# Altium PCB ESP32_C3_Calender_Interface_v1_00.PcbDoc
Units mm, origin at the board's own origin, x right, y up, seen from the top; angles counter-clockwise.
Board outline 63.5 x 22.2 mm, 2 copper layers (Top Layer, Bottom Layer), stack 1.671 mm thick; 38 components, 28 nets, 146 pads, 112 vias.
Unrouted connection lines stored in the file: 57.
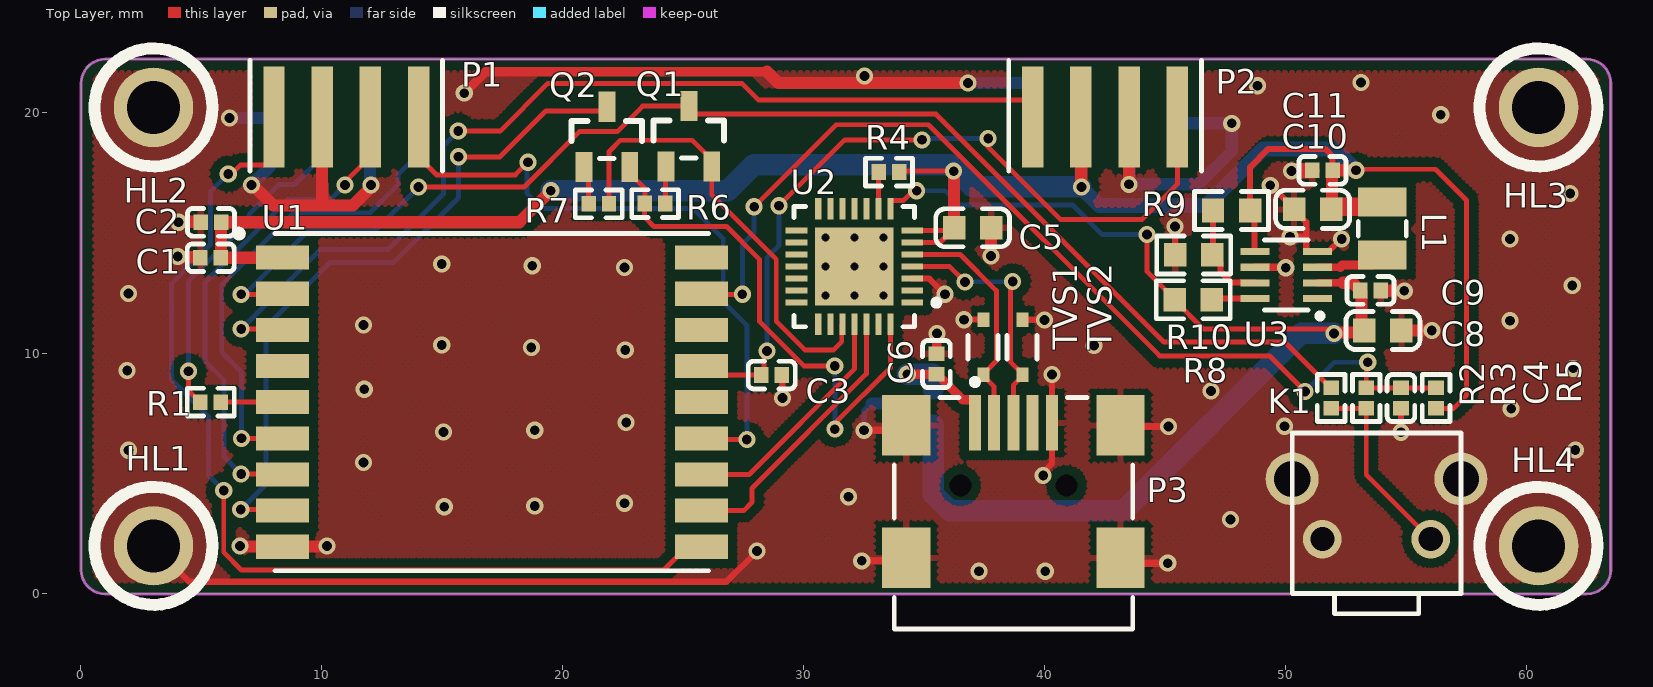
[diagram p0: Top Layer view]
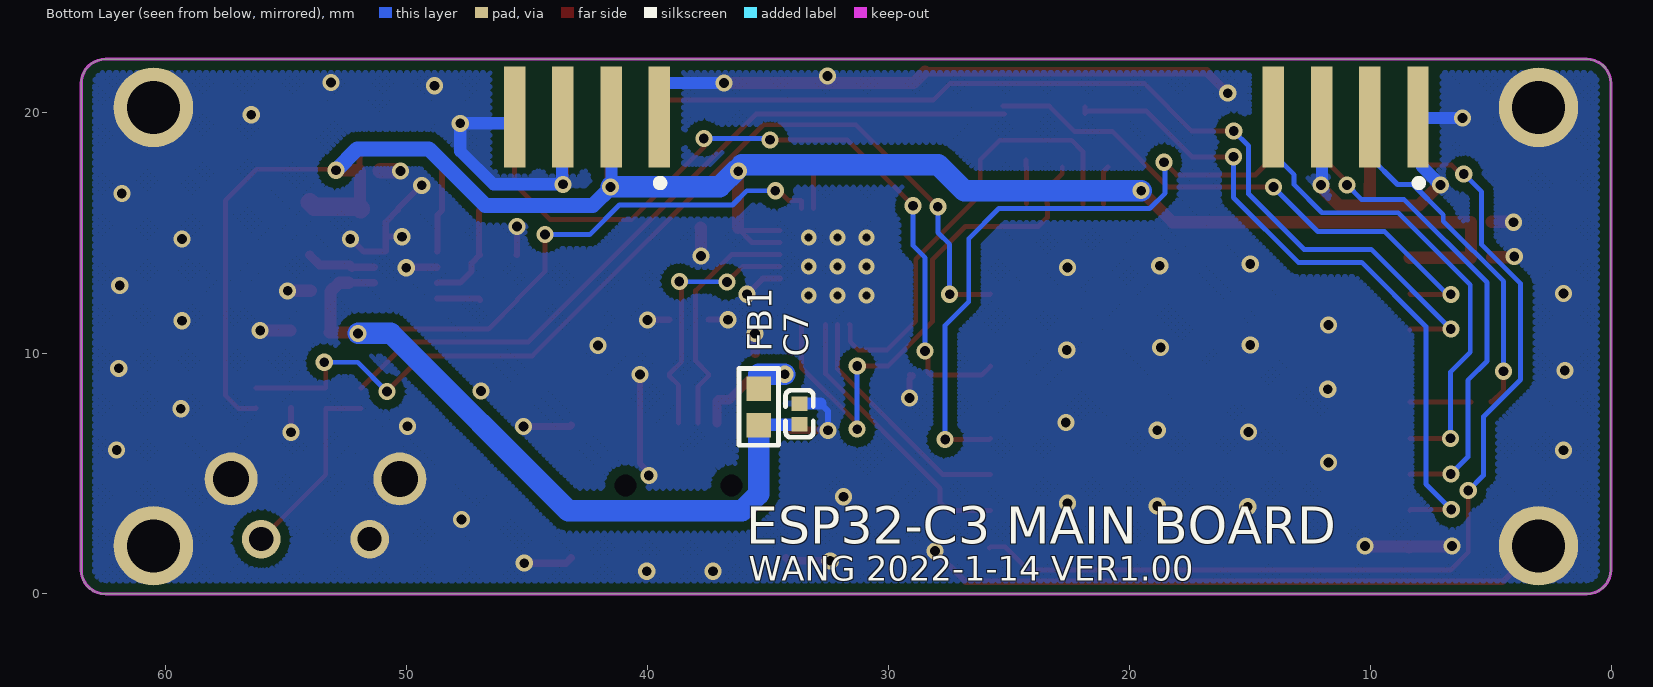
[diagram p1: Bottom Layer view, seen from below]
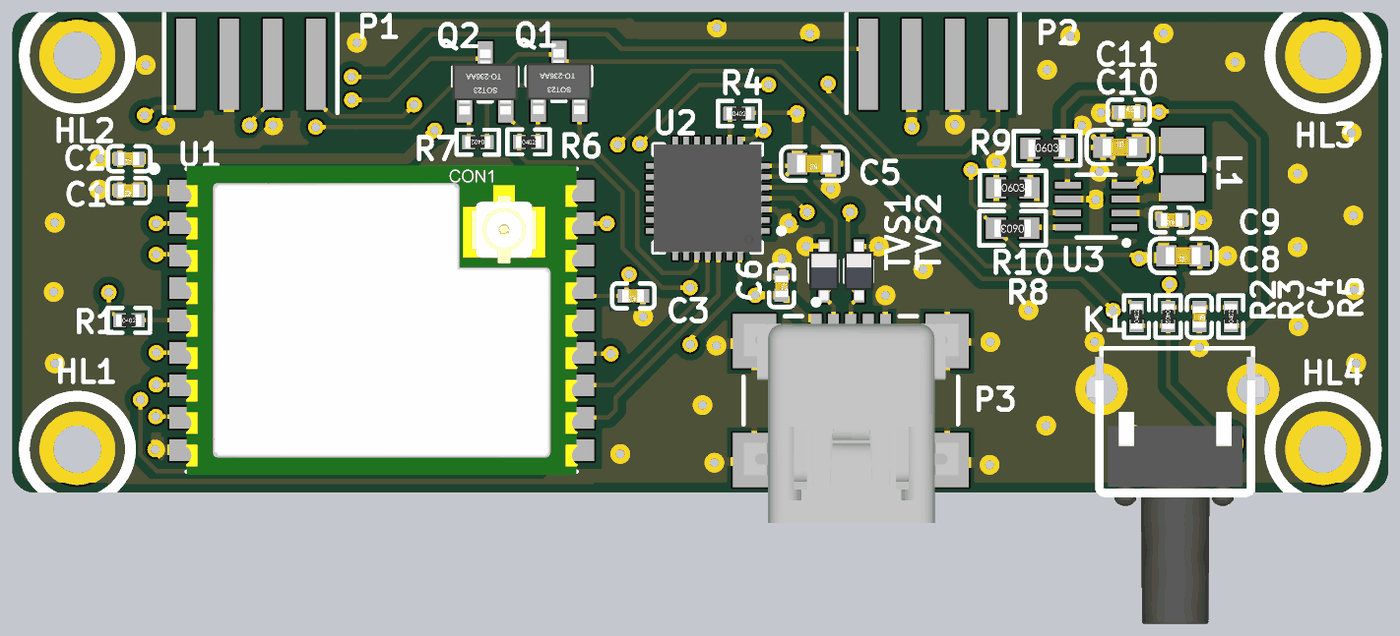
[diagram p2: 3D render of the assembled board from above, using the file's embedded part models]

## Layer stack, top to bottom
Top Solder: solder mask 0.0102, Solder Resist, Dk 3.5
Top Layer: signal copper 0.0356
Dielectric 1: dielectric 1.6, FR-4, Dk 4.8
Bottom Layer: signal copper 0.0356
Bottom Solder: solder mask 0.0102, Solder Resist, Dk 3.5

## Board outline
0.016,1 0.016,21.2 cw(c1.016,21.2) 1.016,22.2 62.516,22.2 cw(c62.516,21.2) 63.516,21.2 63.516,1 cw(c62.516,1) 62.516,0 1.016,0 cw(c1.016,1)

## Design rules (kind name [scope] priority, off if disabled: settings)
Clearance Clearance_1 [InNamedPolygon('GND_TOP') Or  InNamedPolygon('GND_BOTTOM')] p1: gap=0.381 ignorepadtopadclearanceinfootprint=FALSE
Clearance [All] p2: gap=0.152 ignorepadtopadclearanceinfootprint=FALSE
ComponentClearance [All] p1: gap=0.051 collisioncheckmode=3 verticalgap=0 showdistances=FALSE
HoleSize [All] p1: absolutevalues=TRUE maxlimit=5.08 minlimit=0.025 maxpercent=80.000 minpercent=20.000
MinimumSolderMaskSliver [All] p1: minsoldermaskwidth=0
PolygonConnect PolygonConnect_2 [InNet('GND') vs IsThruPin] p1: connectstyle=Direct reliefconductorwidth=0.254 reliefentries=4 polygonreliefangle="90 Angle" airgapwidth=0.254
PolygonConnect PolygonConnect_1 [IsVia] p2: connectstyle=Direct reliefconductorwidth=0.254 reliefentries=4 polygonreliefangle="90 Angle" airgapwidth=0.254
PolygonConnect [All] p3: connectstyle=Relief reliefconductorwidth=0.254 reliefentries=4 polygonreliefangle="90 Angle" airgapwidth=0.254
RoutingVias RoutingVias_1 [InComponent('U1')] p1: holewidth=0.711 width=1.27 viastyle="Through Hole" minholewidth=0.203 minwidth=0.254 maxholewidth=0.711 maxwidth=1.27
RoutingVias [All] p2: holewidth=0.406 width=0.711 viastyle="Through Hole" minholewidth=0.406 minwidth=0.711 maxholewidth=0.711 maxwidth=1.27
SilkToSilkClearance [All] p1: silktosilkclearance=0
SilkToSolderMaskClearance [IsPad] p1: minsilkscreentomaskgap=0 clearancetoexposedcopper=TRUE
SolderMaskExpansion [All] p1: expansion=0.102
Width [All] p1: maxlimit=1.016 minlimit=0.203 preferedwidth=0.254 minimp=50.000000 maximp=50.000000 favimp=50.000000
25 further rules are at their usual default settings.

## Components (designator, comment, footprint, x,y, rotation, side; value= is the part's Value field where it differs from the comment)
C1 "4.7uF (475) 20% 10V" LC-0402_C 5.391,13.958 r180 top
C2 "100nF (104) 10% 16V" LC-0402_C 5.403,15.428 r180 top
C3 "100nF (104) 10% 16V" LC-0402_C 28.679,9.09 r180 top
C4 "100nF (104) 10% 16V" LC-0402_C 54.804,8.132 r270 top
C5 "0.1uF/16V" LC-0603_C 37.023,15.201 r180 top
C6 "100nF (104) 10% 16V" LC-0402_C 35.522,9.549 r270 top
C7 "100nF (104) 10% 16V" LC-0402_C 33.697,7.479 r270 bottom
C8 "10uF (106) 10% 10V" LC-0603_C 54.054,10.938 r180 top
C9 "100nF (104) 10% 16V" LC-0402_C 53.539,12.601 r180 top
C10 "10uF (106) 10% 10V" LC-0603_C 51.136,15.967 r0 top
C11 "100nF (104) 10% 16V" LC-0402_C 51.545,17.585 r0 top
FB1 "Ferrite bread" R0603 35.389,7.764 r90 bottom value=120R@600MHz/500mA
HL1 "D2.0" HOLE_D2.0 3.016,2 r0 top locked
HL2 "D2.0" HOLE_D2.0 3.016,20.2 r0 top locked
HL3 "D2.0" HOLE_D2.0 60.516,20.2 r0 top locked
HL4 "D2.0" HOLE_D2.0 60.516,2 r0 top locked
K1 "BUTTON" BUTTON-TH-6X6-R 53.79,3.475 r0 top locked
L1 "IND" INDM2520X10N 54.027,15.166 r90 top value=1uH/3A
P1 "Header 4X2" HDR2X4-P2-SMD-SIDE-CUSTOM 11.02,17.55 r0 top locked
P2 "Header 4X2" HDR2X4-P2-SMD-SIDE-CUSTOM 42.52,17.55 r0 top locked
P3 "MiniUSB Socket" USB-F-MINI 38.716,7.1 r90 top locked value="mini-USB Socket"
Q1 "SS8050 Y1" LC-SOT-23(SOT-23-3) 25.241,19 r270 top
Q2 "SS8050 Y1" LC-SOT-23(SOT-23-3) 21.836,18.978 r270 top
R1 "22Ω (22R0) ±1%" LC-0402_R 5.391,7.962 r0 top
R2 "0Ω (0R0) ±1%" LC-0402_R 51.904,8.132 r90 top
R3 "0Ω (0R0) ±1%/NC" LC-0402_R 53.365,8.132 r270 top
R4 "4.7KΩ (4701) ±1%" LC-0402_R 33.552,17.517 r0 top
R5 "10KΩ (1002) ±1%" LC-0402_R 56.259,8.132 r90 top
R6 "10KΩ (1002) ±1%" LC-0402_R 23.843,16.207 r0 top
R7 "10KΩ (1002) ±1%" LC-0402_R 21.501,16.196 r180 top
R8 "100KΩ (1003) ±1%" LC-0603_R 46.183,12.212 r180 top
R9 "200KΩ (2003) ±1%" LC-0603_R 47.771,15.918 r0 top
R10 "44.2KΩ (4422) ±1%" LC-0603_R 46.202,14.077 r0 top
TVS1 "PESD3V3L1BA" SOD-323B 37.48,10.242 r90 top
TVS2 "PESD3V3L1BA" SOD-323B 39.092,10.242 r90 top
U1 "ESP32-C3-13U" ESP32-C3-13U 17.062,7.962 r0 top
U2 "CP2102" CP2102 32.113,13.591 r180 top
U3 "MP2161" TSOT23-8 50.043,13.239 r90 top

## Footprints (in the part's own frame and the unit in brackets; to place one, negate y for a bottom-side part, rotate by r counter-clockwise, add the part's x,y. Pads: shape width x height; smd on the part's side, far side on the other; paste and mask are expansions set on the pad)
BUTTON-TH-6X6-R [mm]
  round 1.6 hole 1: 1(-2.25,-1.2) 2(2.25,-1.2)
  round 2.2 hole 1.5: BK1(-3.5,1.3) BK2(3.5,1.3)
  silkscreen extent -3.5,-4.3 3.5,3.2, body extent -4.2,-9.55 4,2.8, height 7.8
CP2102 [mm] "QFN, 28-Leads, Body 5.0x5.0mm (max), Pitch 0.50mm, IPC Medium Density"
  rect 0.9x0.25 smd: 1(-2.4,1.5) 2(-2.4,1) 3(-2.4,0.5) 4(-2.4,0) 5(-2.4,-0.5) 6(-2.4,-1) 7(-2.4,-1.5) 15(2.4,-1.5) 16(2.4,-1) 17(2.4,-0.5) 18(2.4,0) 19(2.4,0.5) 20(2.4,1) 21(2.4,1.5)
  rect 0.25x0.9 smd: 8(-1.5,-2.4) 9(-1,-2.4) 10(-0.5,-2.4) 11(0,-2.4) 12(0.5,-2.4) 13(1,-2.4) 14(1.5,-2.4) 22(1.5,2.4) 23(1,2.4) 24(0.5,2.4) 25(0,2.4) 26(-0.5,2.4) 27(-1,2.4) 28(-1.5,2.4)
  rect 3.25x3.25 smd: 29(0,0)
  silkscreen extent -3.53,-2.5 2.5,2.5, body extent -2.5,-2.5 2.5,2.5, height 1
ESP32-C3-13U [mm] "AI Thinker ESP32-C3-13U Module"
  rect 2.2x1 smd: 1(-8.7,6) 2(-8.7,4.5) 3(-8.7,3) 4(-8.7,1.5) 5(-8.7,0) 6(-8.7,-1.5) 7(-8.7,-3) 8(-8.7,-4.5) 9(-8.7,-6) 10(8.7,-6) 11(8.7,-4.5) 12(8.7,-3) 13(8.7,-1.5) 14(8.7,0) 15(8.7,1.5) 16(8.7,3) 17(8.7,4.5) 18(8.7,6)
  silkscreen extent -10.63,-7 9,7.13, body extent -9.03,-7.15 9.04,7.15, height 3.28
HDR2X4-P2-SMD-SIDE-CUSTOM [mm]
  rect 0.89x4.2 smd far side: 1(-3,2.25) 3(-1,2.25) 5(1,2.25) 7(3,2.25)
  rect 0.89x4.2 smd: 2(-3,2.25) 4(-1,2.25) 6(1,2.25) 8(3,2.25)
  silkscreen extent -4,0 4,4.6
HOLE_D2.0 [mm]
  round 3.3 hole 2.2: 1(0,0)
  silkscreen extent -2.45,-2.45 2.45,2.45
INDM2520X10N [mm] "Molded Inductor, 2-Leads, Body 2.5x2.0mm, IPC Medium Density"
  rect 1.2x2 smd: 1(-1.1,0) 2(1.1,0)
  silkscreen extent -0.3,-1 0.3,1, body extent -1.35,-1.1 1.35,1.1, height 1
LC-0402_C [mm]
  rect 0.6x0.65 smd mask+0.051: 1(-0.425,0) 2(0.425,0)
  silkscreen extent -0.97,-0.58 0.97,0.58, body extent -0.48,-0.3 0.52,0.3, height 0.2
LC-0402_R [mm]
  rect 0.6x0.65 smd mask+0.051: 1(-0.425,0) 2(0.425,0)
  silkscreen extent -0.97,-0.58 0.97,0.58, body extent -0.57,-0.27 0.58,0.28, height 0.41
LC-0603_C [mm]
  rect 0.93x0.98 smd: 1(-0.77,0) 2(0.77,0)
  silkscreen extent -1.53,-0.79 1.54,0.79, body extent -0.8,-0.4 0.8,0.4, height 0.3
LC-0603_R [mm]
  rect 0.93x0.98 smd: 1(-0.77,0) 2(0.77,0)
  silkscreen extent -1.53,-0.79 1.54,0.79, body extent -0.85,-0.4 0.85,0.4, height 0.56
LC-SOT-23(SOT-23-3) [mm]
  rect 1.25x0.7 smd: 1(1.25,-0.95) 2(1.25,0.95) 3(-1.25,0)
  silkscreen extent -0.65,-1.46 0.9,1.46, body extent -1.5,-1.5 1.5,1.5, height 1.3
R0603 [mil]
  rect 40x40 smd: 1(-30,0) 2(30,0)
  silkscreen extent -63,-32 63,32, body extent -39,-15 40,16, height 31
SOD-323B [mm] "bidirectional SOD-323B"
  rect 0.6x0.5 smd: 1(-1.15,0) 2(1.15,0)
  silkscreen extent -0.5,-0.6 0.5,0.65, body extent -1.35,-0.67 1.35,0.67, height 0.79
TSOT23-8 [mm]
  rect 0.3x1.2 smd: 1(-0.975,-1.3) 2(-0.325,-1.3) 3(0.325,-1.3) 4(0.975,-1.3) 5(0.975,1.3) 6(0.325,1.3) 7(-0.325,1.3) 8(-0.975,1.3)
  silkscreen extent -1.8,-1.5 1.45,0.9
USB-F-MINI [mm] "Connector; USB2.0, Type A, SM; 5 Position; Right Angle"
  rect 2.3x0.5 smd: 1(0,1.6) 2(0,0.8) 3(0,0) 4(0,-0.8) 5(0,-1.6)
  rect 2.5x2 smd: 6(-0.1,-4.45) 7(-5.6,-4.45) 8(-0.1,4.45) 9(-5.6,4.45)
  round 0.6 hole 0.9 unplated: MH1(-2.6,-2.2) MH2(-2.6,2.2)
  silkscreen extent -8.55,-4.95 1.82,4.95, body extent -8.5,-4.97 0.7,4.93, height 4.14

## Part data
C1: library part "0402 4.7uF (475) 20% 10V", "贴片电容", Package=0402, SuppliersPartNumber=C23733
C2 C3 C4 C6 C7 C9 C11: library part "0402 100nF (104) 10% 16V", "贴片电容", Package=0402, SuppliersPartNumber=C1525
C5: library part "0603 100nF (104) 10% 50V", "贴片电容", Package=0603, SuppliersPartNumber=C14663
C8 C10: library part "0603 10uF (106) 10% 10V", "贴片电容", Package=0603, SuppliersPartNumber=C19702
FB1: library part FB, "SMD Ferrite bread"
HL1 HL2 HL3 HL4: library part HOLE, "Mechanical Fix Hole"
K1: library part BUTTON2, "Key Button"
L1: "Inductor"
P1 P2: "Header, 4-Pin, Dual row"
P3: library part MINIUSB, "USB 2.0, Right Angle, SMT, A Type, Receptacle, 5 Position, Black", PackageDocument=15-Nov-2002
Q1 Q2: library part "SOT-23 SS8050 Y1", "三极管", Package=SOT-23, SuppliersPartNumber=C2150
R1: library part "0402 22Ω (22R0) 1%", "贴片电阻", Package=0402, SuppliersPartNumber=C25092
R2 R3: library part "0402 0Ω (0R0) 1%", "贴片电阻", Package=0402, SuppliersPartNumber=C17168
R4: library part "0402 4.7KΩ (4701) 1%", "贴片电阻", Package=0402, SuppliersPartNumber=C25900
R5 R6 R7: library part "0402 10KΩ (1002) 1%", "贴片电阻", Package=0402, SuppliersPartNumber=C25744
R8: library part "0603 100KΩ (1003) 1%", "贴片电阻", Package=0603, SuppliersPartNumber=C25803
R9: library part "0603 200KΩ (2003) 1%", "贴片电阻", Package=0603, SuppliersPartNumber=C25811
R10: library part "0603 43KΩ (4302) 1%", "贴片电阻", Package=0603, SuppliersPartNumber=C23172
TVS1 TVS2: "Polymer ESD Devices", Supplier Part Number 1=PESD0603-240TR-ND
U1: "ESP32-C3-13U Module"
U2: "SINGLE-CHIP USB TO UART BRIDGE"
U3: "2A, 6V, 1.5MHz SYNCHRONOUS STEP-DOWN SWITCHER"

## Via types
v1: diameter 0.711, hole 0.406, Top Layer to Bottom Layer, 103 vias
v2: diameter 0.66, hole 0.33, Top Layer to Bottom Layer, tented top, 9 vias

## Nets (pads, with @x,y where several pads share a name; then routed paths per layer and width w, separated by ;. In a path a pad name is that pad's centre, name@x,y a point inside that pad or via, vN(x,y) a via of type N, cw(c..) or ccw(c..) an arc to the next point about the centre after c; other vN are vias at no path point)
+3.3V: C1.1 C2.1 C5.2 C10.2 C11.2 L1.2 P2.3 P2.4 R4.2 R5.1 R9.2 U1.1 U2.6 U2.7 U3.5 | length 95.5
  Top Layer w0.203: R4.2 34.013,17.553 v1(36.235,17.553) ; U2.6 35.667,14.591 36.253,15.176 C5.2 ; U2.7 C5.2@36.142,15.091 ; v1@52.941,17.587 v1(52.943,17.589) 52.985,17.63 56.237,17.63 57.531,16.336 57.531,8.249 56.989,7.707 R5.1 R5.1@56.264,7.713
  Top Layer w0.254: U3.5 48.72,14.237 48.72,15.739 R9.2 48.541,17.716 49.299,18.474 51.654,18.474 51.967,18.16 51.967,17.588 C11.2
  Top Layer w0.508: C1.1 C1.1@5.817,13.96 ; U1.1 8.36,13.96 C1.1@5.817,13.96 ; v1(19.512,16.742) 18.197,15.428 C2.1 5.822,15.422 5.822,13.964 C1.1@5.817,13.96 ; v1(36.235,17.553) 36.244,17.544 36.244,15.21 C5.2 ; P2.4 41.529,19.791 41.529,16.909 v1(41.538,16.9) ; C10.2@51.906,15.992 51.938,16.024 51.938,17.553 C11.2 51.971,17.587 v1@52.941,17.587
  Top Layer w0.762: C10.2 C10.2@51.906,15.992 ; C10.2@51.938,16.024 51.99,16.076 53.836,16.076 L1.2
  Bottom Layer w0.508: v1@41.499,16.908 41.499,19.78 P2.3
  Bottom Layer w0.635: v1@41.508,16.9 42.278,16.129 46.736,16.129 49.081,18.474 52.057,18.474 v1(52.943,17.589)
  Bottom Layer w0.889: v1(19.512,16.742) 26.86,16.742 27.932,17.814 v1@36.1,17.814 ; v1@36.298,17.616 37.014,16.9 v1@41.508,16.9
+5.0V: C7.2 C8.2 C9.2 FB1.1 R8.2 U2.8 U3.2 | length 51.7
  Top Layer w0.203: U2.8 33.613,16.316 33.636,16.339 34.159,16.339 34.557,16.738 v1(34.699,16.738) ; v1(44.266,14.918) 44.266,13.384 45.413,12.237 R8.2 45.413,12.187 46.605,10.996 51.842,10.996 v1(52.021,10.817)
  Top Layer w0.305: U3.2 52.404,12.914 52.406,12.916
  Top Layer w0.508: v1(52.021,10.817) 52.06,10.856 53.201,10.856 53.16,10.896 53.16,12.555 C9.2 53.114,12.626 53.068,12.672 53.043,12.672 52.799,12.916 52.406,12.916
  Bottom Layer w0.203: v1(34.699,16.738) 35.883,16.738 36.475,16.146 41.179,16.146 42.407,14.918 v1(44.266,14.918)
  Bottom Layer w0.508: C7.2 33.723,7.028 35.363,7.028 FB1.1
  Bottom Layer w0.889: FB1.1 35.389,4.147 36.082,3.453 43.293,3.453 50.657,10.817 v1(52.021,10.817)
ENV_LUX_ADC: C3.2 P2.8 U1.15 | length 32.7
  Top Layer w0.203: U1.15 26.134,9.09 C3.2 28.36,9.196 28.36,9.961 v1(28.482,10.083) ; v1(28.979,16.115) 31.717,18.853 v1(34.915,18.853) ; v1(37.667,18.908) 37.667,18.544 40.672,15.539 44.046,15.539 45.52,17.012 P2.8 P2.8@45.483,19.764
  Bottom Layer w0.203: v1(28.482,10.083) 28.482,13.959 28.979,14.455 v1(28.979,16.115) ; v1(34.915,18.853) 34.969,18.908 v1(37.667,18.908)
ESP_EN: Q1.3 R2.2 U1.2 | length 55
  Top Layer w0.203: v1(6.656,12.439) 8.34,12.439 U1.2 ; v1(14.02,16.891) 18.396,16.891 20.696,19.191 22.261,19.191 23.32,20.25 Q1.3 ; Q1.3@25.19,19.924 35.494,19.924 44.957,10.461 49.975,10.461 51.879,8.557 R2.2
  Bottom Layer w0.203: v1(6.656,12.439) 6.801,12.439 9.405,15.043 12.172,15.043 v1(14.02,16.891)
ESP_GPIO9: Q2.3 U1.8 | length 28.9
  Top Layer w0.203: v1(6.638,3.508) 8.316,3.508 U1.8 ; v1(15.682,18.148) 17.4,18.148 19.3,20.049 21.741,20.049 21.836,19.953 Q2.3
  Bottom Layer w0.203: v1(6.638,3.508) 7.686,4.556 7.686,11.096 10.353,13.763 12.984,13.763 15.682,16.461 v1(15.682,18.148)
ESP_UART_RXD: U1.11 U2.26 | length 11.6
  Top Layer w0.203: U1.11 27.514,3.462 27.864,3.812 27.864,4.386 32.613,9.135 U2.26
ESP_UART_TXD: U1.12 U2.25 | length 10
  Top Layer w0.203: U1.12 27.743,4.962 32.113,9.331 U2.25
GND: C1.2 C2.2 C3.1 C4.2 C5.1 C6.1 C7.1 C8.1 C9.1 C10.1 C11.1 HL1.1 HL2.1 HL3.1 HL4.1 K1.1 K1.BK1 K1.BK2 P1.1 P1.4 P1.5 P2.1 P2.5 P2.6 P2.7 P3.5 P3.6 P3.7 P3.8 P3.9 R10.1 TVS1.2 TVS2.2 U1.9 U2.3 U2.29 U3.4 U3.6 | length 121.3
  Top Layer w0.203: P2.6@43.518,19.746 43.492,19.773 P2.6 ; C9.1 C9.1@53.981,12.584
  Top Layer w0.254: HL1.1 4.509,0.507 26.802,0.507 v1(28.075,1.78) ; v1(4.021,14.008) v1@4.046,13.983 ; v1(4.058,15.431) v1@4.075,15.448 ; C1.2@4.94,13.983 C1.2 ; C2.2@4.957,15.448 C2.2 ; P1.4@10.014,19.794 P1.4 ; C3.1@28.998,9.083 28.978,9.064 29.13,8.912 v1(29.13,8.13) ; C3.1 C3.1@29.111,9.083 ; U2.3 34.515,13.089 35.225,13.089 v1(35.874,12.44) ; C6.1 C6.1@35.53,9.982 ; v1@35.53,10.809 v1(35.538,10.817) ; v1(36.659,11.383) 36.663,11.387 37.475,11.387 TVS1.2 ; TVS2.2 39.102,11.382 40.001,11.382 v1(40.011,11.372) ; v1(39.95,4.923) 39.95,5.047 40.316,5.413 P3.5 ; P3.5 v1(40.317,9.115) ; v1(45.426,15.256) 45.426,14.083 R10.1 ; v1(49.375,16.965) 49.392,16.965 50.366,15.992 C10.1 50.366,15.942 50.87,15.437 50.87,14.837 ; v1(50.196,14.828) 50.205,14.837 50.87,14.837 ; v1(50.262,17.556) v1@50.276,17.571 ; C11.1@51.105,17.571 C11.1 ; v1(52.342,14.736) 52.315,14.736 51.793,14.214 U3.4 50.893,14.214 50.87,14.237 50.87,14.837 ; v1(54.804,6.713) C4.2
  Top Layer w0.305: v1(32.417,1.375) 34.141,1.375 P3.9 ; v1(32.513,6.793) 34.059,6.793 P3.8 ; P3.7 43.388,1.279 v1(45.122,1.279) ; P3.6 43.212,6.954 v1(45.154,6.954) ; U3.6 48.745,13.562 50.004,13.562 v1(50.021,13.545)
  Top Layer w0.381: v1(15.916,20.791) 16.805,21.68 28.484,21.68 ; C6.1@35.53,9.982 v1@35.53,10.809
  Top Layer w0.508: v1@4.046,13.983 C1.2@4.94,13.983 ; v1@4.075,15.448 C2.2@4.957,15.448 ; v1(6.602,1.985) 6.614,1.974 8.35,1.974 U1.9 ; v1(7.083,16.977) 7.138,16.977 7.985,16.129 10.02,16.129 ; U1.9@8.397,1.927 U1.9 ; P1.4@10.014,19.794 10.014,16.997 10.02,16.991 10.02,16.129 ; v1(10.215,1.985) 10.203,1.974 8.374,1.974 U1.9 ; v1@12.046,17.017 12.046,16.886 11.289,16.129 10.02,16.129 ; 28.484,21.68 28.955,21.209 v1(36.83,21.209) ; v1(37.786,14.032) 37.786,15.195 C5.1 ; v1(43.518,17.006) P2.6@43.518,19.746 ; C9.1@53.981,12.584 v1(54.944,12.584) ; C8.1 v1@56.085,10.938
  Top Layer w0.635: v1@50.276,17.571 C11.1@51.105,17.571
  Bottom Layer w0.203: P2.1@39.176,21.209 39.52,20.866 P2.1 P2.1@39.497,19.777 ; P2.5 43.504,19.784 P2.5@43.55,19.738 ; P2.7 P2.7@45.781,19.539
  Bottom Layer w0.254: P1.1@7.874,19.655 7.98,19.761 P1.1 ; P1.5@12.001,19.782 P1.5 ; v1(32.513,6.793) 32.513,7.598 32.818,7.904
  Bottom Layer w0.508: v1(6.168,19.761) P1.1@7.98,19.761 ; v1(7.083,16.977) 7.874,17.768 P1.1@7.874,19.655 ; v1@12.001,17.061 P1.5@12.001,19.782 ; 32.818,7.904 C7.1 ; v1(36.83,21.209) P2.1@39.176,21.209 ; v1(43.518,17.006) 46.402,17.006 47.779,18.383 v1(47.779,19.539) P2.7@45.781,19.539 ; v1@43.55,17.106 P2.5@43.55,19.738
  other v1: 37.289,0.944 40.039,0.944 47.732,3.093 15.089,3.62 18.846,3.656 22.567,3.764 31.873,4.038 11.729,5.462 1.975,5.967 62.043,5.972 15.053,6.727 18.846,6.799 49.967,6.961 22.639,7.124 59.379,7.691 46.915,8.422 11.765,8.497 1.923,9.272 61.957,9.368 22.603,10.123 18.701,10.231 42.059,10.313 14.98,10.339 56.085,10.937 11.729,11.17 59.336,11.345 1.975,12.473 61.914,12.806 22.567,13.555 18.738,13.627 14.98,13.699 59.336,14.74 61.829,16.631 12.046,16.977 56.456,19.897 48.849,21.1 53.147,21.229 32.535,21.499
  other v2: 30.913,12.391 32.113,12.391 33.313,12.391 30.913,13.591 32.113,13.591 33.313,13.591 30.913,14.791 32.113,14.791 33.313,14.791
LCD_BK: P2.2 U1.3 | length 41
  Top Layer w0.203: v1(6.656,10.999) 8.325,10.999 U1.3 ; v1(15.669,19.216) 17.409,19.216 19.39,21.197 27.443,21.197 28.138,20.501 39.52,20.501 P2.2
  Bottom Layer w0.203: v1(6.656,10.999) 9.964,14.307 12.75,14.307 15.053,16.61 15.053,18.6 v1(15.669,19.216)
LCD_CSn: P1.2 U1.10 | length 42.1
  Top Layer w0.203: v1(5.93,4.292) 5.93,1.728 6.67,0.988 24.189,0.988 25.162,1.962 U1.10 U1.10@25.817,1.907 ; v1(6.12,17.437) 6.257,17.437 6.622,17.802 7.676,17.802 8.02,18.145 P1.2
  Bottom Layer w0.203: v1(5.93,4.292) 5.3,4.923 5.3,7.363 3.758,8.904 3.758,12.882 5.374,14.499 5.374,16.692 v1(6.12,17.437)
LCD_DC: P1.6 U1.7 | length 21
  Top Layer w0.203: v1(6.656,4.981) 8.342,4.981 U1.7 ; v1(10.963,16.977) 10.963,17.089 12.02,18.145 P1.6
  Bottom Layer w0.203: v1(6.656,4.981) 5.949,5.688 5.949,8.868 5.156,9.661 5.156,12.934 8.604,16.381 10.368,16.381 v1(10.963,16.977)
LCD_RESETn: P1.8 U1.13 | length 27.6
  Top Layer w0.203: P1.8 14.02,18.145 14.766,17.399 18.042,17.399 v1(18.563,17.921) ; U1.13 25.815,6.409 v1(27.648,6.409)
  Bottom Layer w0.203: v1(18.563,17.921) 18.519,17.877 18.519,16.64 19.158,16.002 25.42,16.002 26.67,14.752 26.67,12.125 27.648,11.147 v1(27.648,6.409)
LCD_SCL: P1.3 R1.1 | length 14.8
  Top Layer w0.203: v1(4.465,9.246) 4.465,8.462 R1.1 R1.1@4.992,7.988
  Bottom Layer w0.203: v1(4.465,9.246) 4.465,12.977 6.968,15.48 6.968,15.741 8.225,16.997 8.872,16.997 10.02,18.145 P1.3
LCD_SDA: P1.7 U1.6 | length 20.6
  Top Layer w0.203: v1(6.664,6.461) U1.6@8.361,6.461
  Bottom Layer w0.203: v1(6.664,6.461) 6.664,9.221 5.85,10.035 5.85,12.836 8.842,15.827 12.002,15.827 13.162,16.987 13.162,17.399 14.02,18.257 P1.7
NetK1_2: K1.2 R2.1 R3.2 | length 8
  Top Layer w0.203: R2.1 R3.2 53.365,4.951 K1.2
NetL1_1: L1.1 U3.3 | length 2.9
  Top Layer w0.305: U3.3 51.345,13.562 52.284,13.562
  Top Layer w0.381: 52.284,13.562 52.379,13.657 53.618,13.657 L1.1
NetQ1_1: Q1.1 R6.2 | length 1.8
  Top Layer w0.203: R6.2 24.268,17.727 Q1.1 Q1.1@24.291,18.025
NetQ2_1: Q2.1 R7.2 | length 1.6
  Top Layer w0.203: Q2.1 21.076,17.538 R7.2
NetR1_2: R1.2 U1.5 | length 2.5
  Top Layer w0.203: R1.2 U1.5
NetR4_1: R4.1 U2.9 | length 1.5
  Top Layer w0.203: U2.9 33.12,15.998 33.12,17.51 R4.1
NetR8_1: R8.1 U3.8 | length 1.8
  Top Layer w0.254: R8.1 47.005,12.264 U3.8
NetR9_1: R9.1 R10.2 U3.7 | length 4.3
  Top Layer w0.254: R9.1 47.001,14.106 R10.2 47.31,13.739 47.31,13.388 47.762,12.935 48.722,12.935 U3.7
UART_DTR: Q2.2 R6.1 U2.28 | length 22.3
  Top Layer w0.203: Q2.2 22.786,17.453 23.403,16.837 23.418,16.837 R6.1 23.405,16.194 23.405,15.636 23.787,15.253 26.814,15.253 28.169,13.898 28.169,11.314 30.014,9.469 v1(31.301,9.469) ; v1(31.301,6.841) 31.301,7.085 33.613,9.397 U2.28
  Bottom Layer w0.203: v1(31.301,6.841) v1(31.301,9.469)
UART_RTS: Q1.2 R7.1 U2.24 | length 18.9
  Top Layer w0.203: R7.1 21.926,18.365 22.397,18.836 25.38,18.836 26.191,18.025 Q1.2 26.191,16.571 28.868,13.894 28.868,11.322 30.055,10.135 31.252,10.135 31.589,10.473 31.589,11.167 U2.24
USB_D+: P3.3 TVS2.1 U2.4 | length 10.7
  Top Layer w0.203: U2.4 36.066,13.591 v1(36.703,12.954) ; v1(38.683,12.972) 38.588,12.877 38.588,9.646 39.092,9.142 TVS2.1 39.092,9.042 38.716,8.666 P3.3
  Bottom Layer w0.203: v1(36.703,12.954) 36.712,12.963 38.674,12.963 v1(38.683,12.972)
USB_D-: P3.2 TVS1.1 U2.5 | length 10
  Top Layer w0.203: U2.5 36.508,14.091 38.008,12.591 38.008,9.67 37.48,9.142 TVS1.1 37.48,9.042 37.916,8.606 P3.2
USB_VBUS: C6.2 FB1.2 P3.1 | length 6.3
  Top Layer w0.381: v1(34.308,9.119) 34.31,9.122 35.519,9.122 C6.2 35.547,9.124 36.611,8.059 37.057,8.059 37.116,8 P3.1
  Bottom Layer w0.381: FB1.2@35.071,8.844 FB1.2
  Bottom Layer w0.889: v1(34.308,9.119) 35.389,9.119 FB1.2
USR_BTNn: C4.1 R3.1 R5.2 U1.17 | length 41.5
  Top Layer w0.203: U1.17 25.784,12.44 v1(27.461,12.44) ; v1(27.952,16.076) 31.354,19.477 35.188,19.477 44.783,9.882 49.347,9.882 v1(50.825,8.405) ; v1(53.428,9.621) 53.365,9.558 R3.1 R5.2
  Bottom Layer w0.203: v1(27.461,12.44) 27.461,14.514 27.952,15.006 v1(27.952,16.076) ; v1(50.825,8.405) 52.04,9.621 v1(53.428,9.621)
pads on no net: P3.4 P3.MH1 P3.MH2 U1.4 U1.14 U1.16 U1.18 U2.1 U2.2 U2.10 U2.11 U2.12 U2.13 U2.14 U2.15 U2.16 U2.17 U2.18 U2.19 U2.20 U2.21 U2.22 U2.23 U2.27 U3.1

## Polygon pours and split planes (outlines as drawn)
GND on Bottom Layer "GND_BOTTOM" (hatched 45Degree grid 0.203 track 0.203, remove dead copper, pour order 2): 0.016,0 63.503,0 63.503,22.2 0.016,22.2
GND on Top Layer "GND_TOP" (hatched 45Degree grid 0.203 track 0.203, remove dead copper, pour order 0): 0.016,0 63.516,0 63.516,22.2 0.016,22.2

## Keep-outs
Keep-Out Layer:
  the board outline again, w0.127

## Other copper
Top Layer:
  pour cut-out: 53.05,16.879 53.017,16.879 53.017,13.455 55.037,13.455 55.037,16.879 53.05,16.879
  pour cut-out: 38.517,22.192 38.517,17.565 46.532,17.565 46.532,22.193 38.516,22.193
  pour cut-out: 7.017,22.201 7.017,17.552 15.032,17.552 15.032,22.201 7.017,22.201
Bottom Layer:
  pour cut-out: 38.516,22.2 46.532,22.2 46.532,17.553 38.52,17.553
  pour cut-out: 7.023,22.2 15.02,22.2 15.02,17.596 7.02,17.596

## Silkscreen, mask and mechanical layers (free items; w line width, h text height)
Bottom Overlay:
  text "ESP32-C3 MAIN BOARD" at 35.916,2.082 h1.52
  text "WANG 2022-1-14 VER1.00" at 35.801,0.546 h1.02
Mechanical 1:
  the board outline again, w0.127
Mechanical 15:
  drawing of 2287 lines, arcs and shapes, not listed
